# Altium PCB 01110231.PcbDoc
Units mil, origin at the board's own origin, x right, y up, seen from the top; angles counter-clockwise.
Board outline 3350 x 4325 mil, 2 copper layers (Top Layer, Bottom Layer); 143 components, 61 nets, 314 pads, 19 vias.
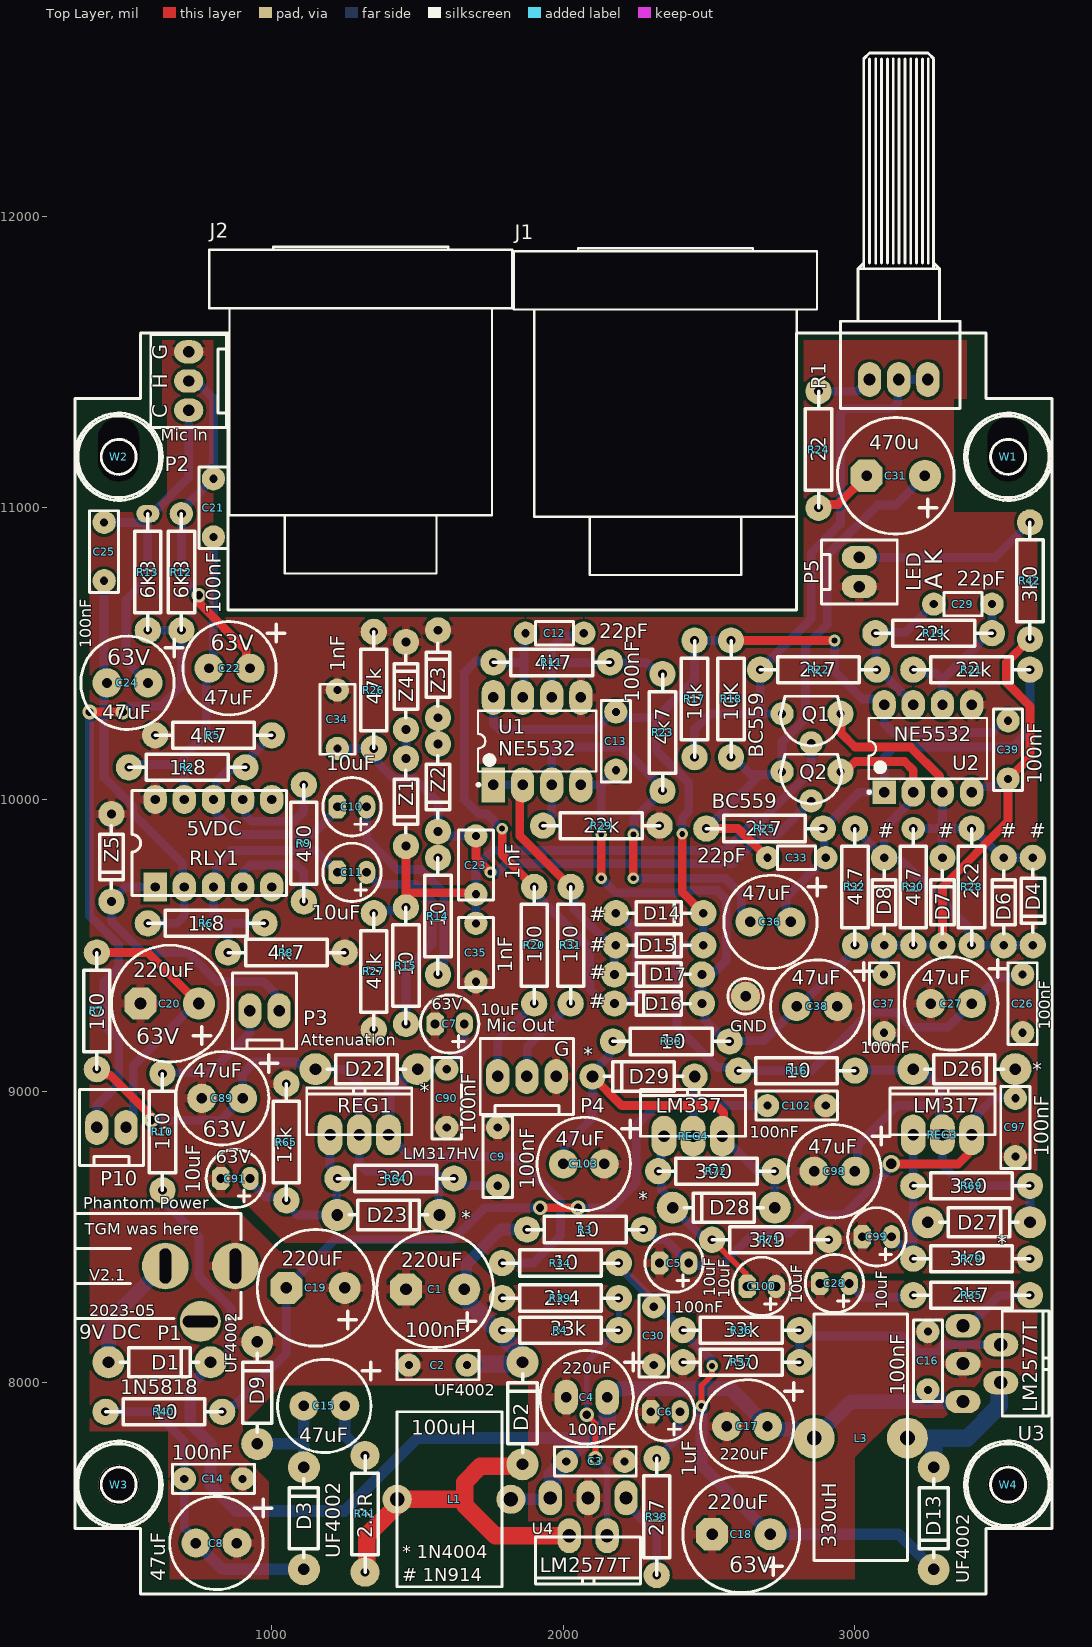
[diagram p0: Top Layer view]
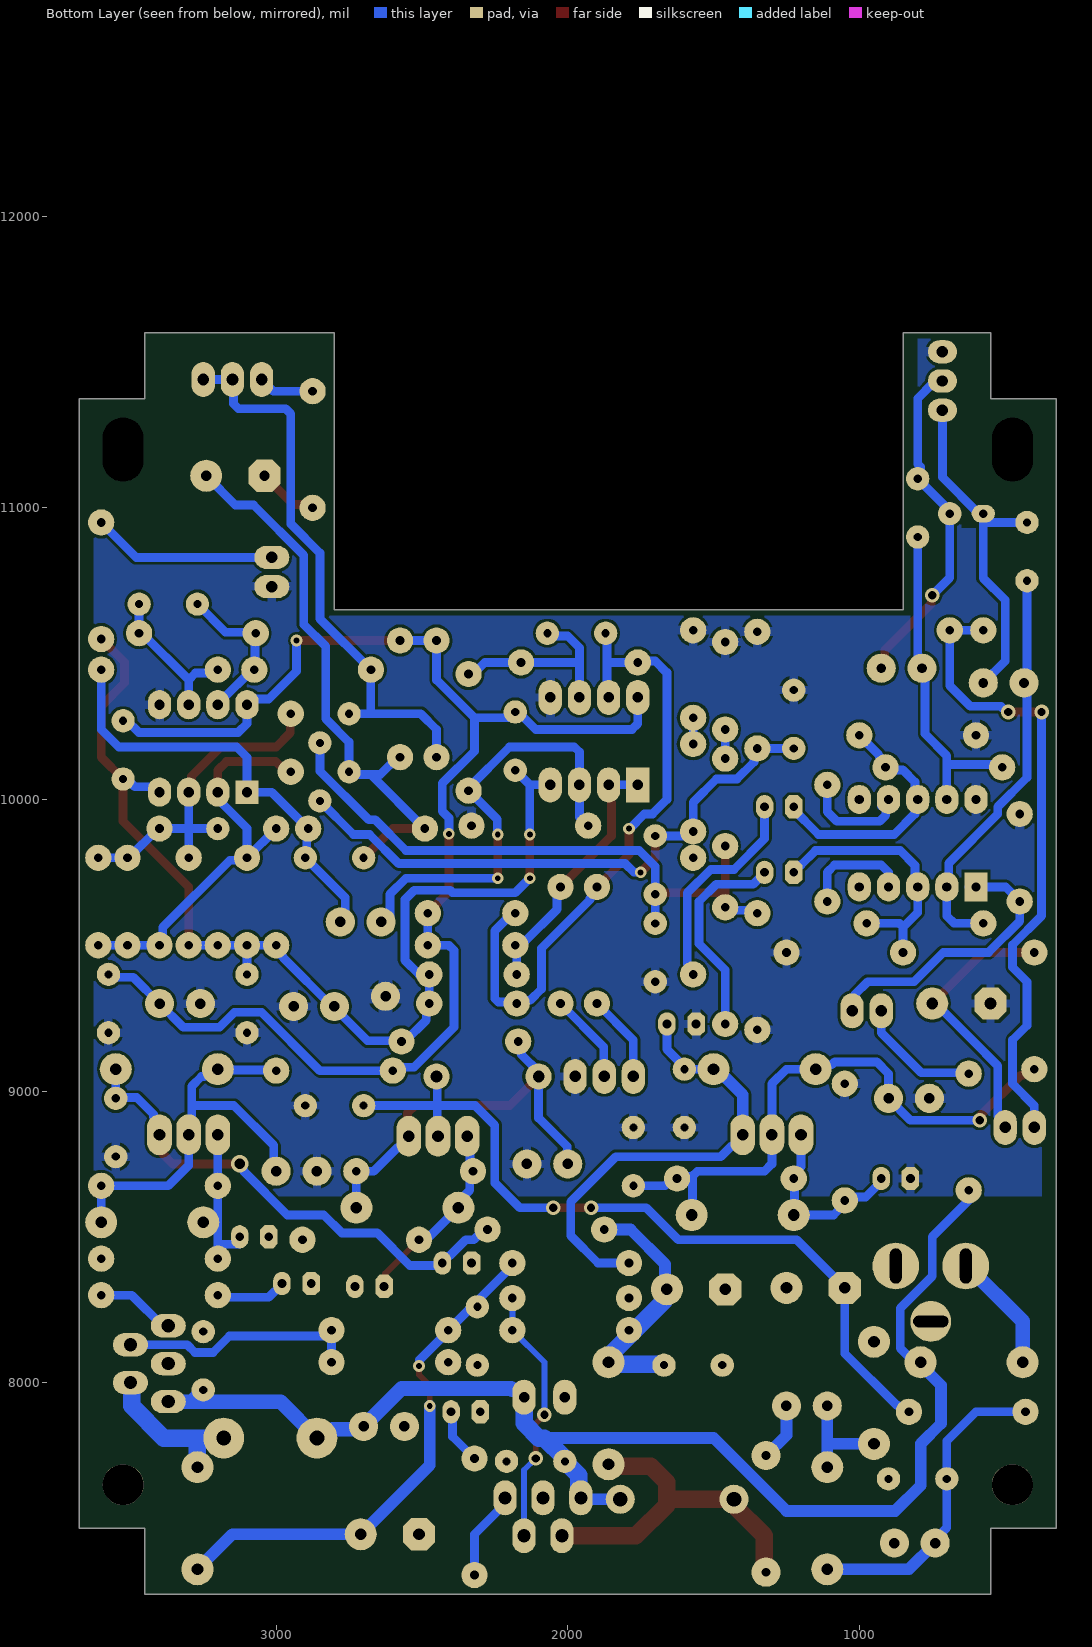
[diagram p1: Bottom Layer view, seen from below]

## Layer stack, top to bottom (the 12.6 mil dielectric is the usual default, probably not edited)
Top Solder: solder mask 0.4, Solder Resist, Dk 3.5
Top Layer: signal copper 1.4
Dielectric1: dielectric 12.6, FR-4, Dk 4.8
Bottom Layer: signal copper 1.4
Bottom Solder: solder mask 0.4, Solder Resist, Dk 3.5

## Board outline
325,7500 550,7500 550,7275 3450,7275 3450,7500 3675,7500 3675,11375 3450,11375 3450,11600 2800,11600 2800,10650 850,10650 850,11600 550,11600 550,11375 325,11375

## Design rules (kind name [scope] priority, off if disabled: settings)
Clearance Clearance_1 [All] p1: gap=10 ignorepadtopadclearanceinfootprint=TRUE
Clearance Clearance_poly [(IsRegion)] p2: gap=10 ignorepadtopadclearanceinfootprint=FALSE
DiffPairsRouting [All] p1: maxlimit=10 minlimit=10 mostfreqgap=10 toplayer_minwidth=15 toplayer_maxwidth=15 toplayer_prefwidth=15 bottomlayer_minwidth=15 bottomlayer_maxwidth=15 bottomlayer_prefwidth=15 substack1={E4759729-C15E-44EF-B839-1660CB1699A4} toplayer_{e4759729-c15e-44ef-b839-1660cb1699a4}_minwidth=15 toplayer_{e4759729-c15e-44ef-b839-1660cb1699a4}_maxwidth=15 toplayer_{e4759729-c15e-44ef-b839-1660cb1699a4}_prefwidth=15 bottomlayer_{e4759729-c15e-44ef-b839-1660cb1699a4}_minwidth=15 bottomlayer_{e4759729-c15e-44ef-b839-1660cb1699a4}_maxwidth=15 bottomlayer_{e4759729-c15e-44ef-b839-1660cb1699a4}_prefwidth=15 substack2={AF7D8FCE-D8A9-40D7-8453-C7F108753530} toplayer_{af7d8fce-d8a9-40d7-8453-c7f108753530}_minwidth=15 toplayer_{af7d8fce-d8a9-40d7-8453-c7f108753530}_maxwidth=15 toplayer_{af7d8fce-d8a9-40d7-8453-c7f108753530}_prefwidth=15 bottomlayer_{af7d8fce-d8a9-40d7-8453-c7f108753530}_minwidth=15 bottomlayer_{af7d8fce-d8a9-40d7-8453-c7f108753530}_maxwidth=15 bottomlayer_{af7d8fce-d8a9-40d7-8453-c7f108753530}_prefwidth=15 maxuncoupledlength=500
Height [All] p1: minheight=0 maxheight=1130 prefheight=500
HoleSize [All] p1: absolutevalues=TRUE maxlimit=400 minlimit=1 maxpercent=80.000 minpercent=20.000
PlaneConnect [All] p1: planeconnectstyle=Relief reliefexpansion=20 reliefentries=4 reliefconductorwidth=30 reliefairgap=10
PolygonConnect [All] p1: connectstyle=Relief reliefconductorwidth=30 reliefentries=4 polygonreliefangle="90 Angle" airgapwidth=10
RoutingVias [All] p1: holewidth=16 width=32 viastyle="Through Hole" minholewidth=8 minwidth=16 maxholewidth=200 maxwidth=200
SilkToSolderMaskClearance SilkscreenOverComponentPads [IsPad] p1: minsilkscreentomaskgap=10 clearancetoexposedcopper=TRUE
SolderMaskExpansion [All] p1: expansion=4 istentingtop=FALSE
Width [All] p1: maxlimit=250 minlimit=10 preferedwidth=40 substack1={E4759729-C15E-44EF-B839-1660CB1699A4} substack2={AF7D8FCE-D8A9-40D7-8453-C7F108753530}
25 further rules are at their usual default settings.

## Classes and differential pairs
component class "RESPIN Mic Interface": C10 C11 C12 C13 C20 C21 C22 C23 C24 C25 C26 C27 C29 C31 C33 C34 C35 C36 C37 C38 C39 D4 D6 D7 D8 D14 D15 D16 D17 J1 J2 P2 P3 P4 P5 P10 Q1 Q2 R1 R2 R5 R6 R7 R8 R9 R10 R11 R12 R13 R14 R15 R16 R17 R18 R19 R20 R21 R22 R23 R24 R25 R26 R27 R28 R29 R30 R31 R32 R33 R42 RLY1 U1 U2 Z1 Z2 Z3 Z4 Z5
component class "RESPIN Power Supply": C1 C2 C3 C4 C5 C6 C7 C8 C9 C14 C15 C16 C17 C18 C19 C28 C30 C89 C90 C91 C97 C98 C99 C100 C102 C103 D1 D2 D3 D9 D13 D22 D23 D26 D27 D28 D29 F2 L1 L3 L6 P1 R3 R4 R34 R35 R36 R37 R38 R39 R40 R41 R64 R65 R69 R70 R71 R72 REG1 REG3 REG4 U3 U4 W1 W2 W3 W4

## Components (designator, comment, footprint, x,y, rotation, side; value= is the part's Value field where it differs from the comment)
C1 "220uF" RB.2/.4#1 1660,8320 r0 top
C2 "100nF" AXIAL0.2-2.5mm-CAP 1670,8060 r180 top
C3 "100nF" AXIAL0.2-2.5mm-CAP 2010,7730 r0 top
C4 "220uF" RB3.5/8mm#1 2150,7950 r180 top
C5 "10uF" RB.1/.2-PTH 2430,8410 r0 top
C6 "1uF" RB.1/.2-PTH 2400,7900 r0 top
C7 "10uF" RB.1/.2-PTH 1660,9230 r0 top
C8 "47uF" RB3.5/8mm#2 880,7450 r180 top
C9 "100nF" AXIAL0.2-2.5mm-CAP 1775,8675 r90 top
C10 "10uF" RB.1/.2-PTH 1325,9975 r0 top
C11 "10uF" RB.1/.2-PTH 1325,9750 r0 top
C12 "22pF" AXIAL0.2 1870,10570 r0 top
C13 "100nF" AXIAL0.2-2.5mm-CAP 2180,10300 r270 top
C14 "100nF" AXIAL0.2-2.5mm-CAP 700,7670 r0 top
C15 "47uF" RB3.5/8mm#2 1250,7920 r180 top
C16 "100nF" AXIAL0.2-2.5mm-CAP 3250,7975 r90 top
C17 "220uF" RB3.5/8mm#2 2700,7850 r180 top
C18 "220uF" RB.2/.4#1 2710,7480 r0 top
C19 "220uF" RB.2/.4#1 1250,8325 r0 top
C20 "220uF" RB.2/.4#1 750,9300 r0 top
C21 "100nF" AXIAL0.2-2.5mm-CAP 800,11100 r270 top
C22 "47uF" RB3.5/8MM 925,10450 r180 top
C23 "1nF" AXIAL0.2-CAP 1700,9675 r90 top
C24 "47uF" RB3.5/8MM 575,10400 r180 top
C25 "100nF" AXIAL0.2-2.5mm-CAP 425,10950 r270 top
C26 "100nF" AXIAL0.2-2.5mm-CAP 3575,9400 r270 top
C27 "47uF" RB3.5/8mm#2 3400,9300 r180 top
C28 "10uF" RB.1/.2-PTH 2980,8340 r0 top
C29 "22pF" AXIAL0.2 3270,10670 r0 top
C30 "100nF" AXIAL0.2-2.5mm-CAP 2310,8260 r270 top
C31 "470u" RB.2/.4#2 3240,11110 r0 top
C33 "22pF" AXIAL0.2 2700,9800 r0 top
C34 "1nF" AXIAL0.2-CAP 1225,10375 r270 top
C35 "1nF" AXIAL0.2-CAP 1700,9375 r90 top
C36 "47uF" RB3.5/8mm#2 2780,9580 r180 top
C37 "100nF" AXIAL0.2-2.5mm-CAP 3100,9200 r90 top
C38 "47uF" RB3.5/8mm#2 2940,9290 r180 top
C39 "100nF" AXIAL0.2-2.5mm-CAP 3524.99,10270.01 r270 top
C89 "47uF" RB3.5/8mm#2 900,8975 r180 top
C90 "100nF" AXIAL0.2-2.5mm-CAP 1600,9075 r270 top
C91 "10uF" RB.1/.2-PTH 925,8700 r0 top
C97 "100nF" AXIAL0.2-2.5mm-CAP 3550,8975 r270 top
C98 "47uF" RB3.5/8mm#2 3000,8725 r180 top
C99 "10uF" RB.1/.2-PTH 3125,8500 r0 top
C100 "10uF" RB.1/.2-PTH 2730,8330 r0 top
C102 "100nF" AXIAL0.2-2.5mm-CAP 2900,8950 r180 top
C103 "47uF" RB3.5/8mm#2 2140,8750 r180 top
D1 "1N5818" DIODE0.35-TH#1 440,8070 r0 top
D2 "UF4002" DIODE0.35-TH#1 1860,7720 r90 top
D3 "UF4002" DIODE0.35-TH#1 1110,7360 r90 top
D4 "1N914" "DIODE0.3-TH - AK" 3610,9800 r270 top
D6 "1N914" "DIODE0.3-TH - AK" 3510,9500 r90 top
D7 "1N914" "DIODE0.3-TH - AK" 3300,9500 r90 top
D8 "1N914" "DIODE0.3-TH - AK" 3100,9500 r90 top
D9 "UF4002" DIODE0.35-TH#1 950,7790 r90 top
D13 "UF4002" DIODE0.35-TH#1 3270,7710 r270 top
D14 "1N914" "DIODE0.3-TH - AK" 2180,9610 r0 top
D15 "1N914" "DIODE0.3-TH - AK" 2180,9500 r0 top
D16 "1N914" "DIODE0.3-TH - AK" 2475,9300 r180 top
D17 "1N914" "DIODE0.3-TH - AK" 2475,9400 r180 top
D22 "1N4004" DIODE0.35-TH#1 1150,9075 r0 top
D23 "1N4004" DIODE0.35-TH#1 1225,8575 r0 top
D26 "1N4004" DIODE0.35-TH#1 3200,9075 r0 top
D27 "1N4004" DIODE0.35-TH#1 3250,8550 r0 top
D28 "1N4004" DIODE0.35-TH#1 2725,8600 r180 top
D29 "1N4004" DIODE0.35-TH#2 2450,9050 r180 top
J1 "XLR Panel Socket" "XLR_3 - Altronics P0850" 2350,10600 r0 top
J2 "XLR Panel Plug" "XLR_3 - Altronics P0850" 1305,10605 r0 top
L1 "100uH" INDUCTOR15MMx9MM-VERT 1790,7600 r180 top
L3 "330uH" INDUCTOR21mmx8mm-VERT 2860,7810 r0 top
P1 "Power" "2.1MM SOCKET" 875,8400 r180 top
P2 "Mic In" "HEADER 3 SIL"#1 715,11535 r270 top
P3 "Attenuation" "HEADER 2 SIL" 1025,9275 r180 top
P4 "Mic Out" "HEADER 3 SIL"#2 1975,9050 r180 top
P5 "LED" "Header 2 SIL" 3015,10730 r90 top
P10 "Phantom Power" "HEADER 2 SIL" 500,8875 r180 top
Q1 "BC559" TO-92BIG 2850,10193.87 r270 top
Q2 "BC559" TO-92BIG 2850,9995 r270 top
R1 "10K Reverse Log" "POT_Small_Single - TT Single Horizontal" 3150,11440 r180 top
R2 "1k8" AXIAL0.4#1 910,10110 r180 top
R3 "10" AXIAL0.4#1 1875,8525 r0 top
R4 "33k" AXIAL0.4#1 2190,8180 r180 top
R5 "4k7" AXIAL0.4#1 1000,10220 r180 top
R6 "1k8" AXIAL0.4#1 975,9575 r180 top
R7 "100" AXIAL0.4#1 400,9075 r90 top
R8 "4k7" AXIAL0.4#1 850,9475 r0 top
R9 "430" AXIAL0.4#1 1110,10050 r270 top
R10 "150" AXIAL0.4#1 625,9059.69 r270 top
R11 "4k7" AXIAL0.4#1 1760,10470 r0 top
R12 "6K8" AXIAL0.4#2 690,10980 r270 top
R13 "6K8" AXIAL0.4#3 575,10980 r270 top
R14 "10" AXIAL0.4#1 1570,9400 r90 top
R15 "10" AXIAL0.4#1 1460,9230 r90 top
R16 "10" AXIAL0.4#1 3000,9070 r180 top
R17 "10k" AXIAL0.4#1 2450,10145 r90 top
R18 "10K" AXIAL0.4#1 2575,10145 r90 top
R19 "22k" AXIAL0.4#1 3070,10570 r0 top
R20 "100" AXIAL0.4#1 1900,9700 r270 top
R21 "22k" AXIAL0.4#1 3200,10445 r0 top
R22 "2k7" AXIAL0.4#1 2675,10445 r0 top
R23 "4k7" AXIAL0.4#1 2340,10430 r270 top
R24 "22" AXIAL0.4#1 2875,11400 r270 top
R25 "2k7" AXIAL0.4#1 2490,9900 r0 top
R26 "47k" AXIAL0.4#1 1350,10175 r90 top
R27 "47k" AXIAL0.4#1 1350,9610 r270 top
R28 "2k2" AXIAL0.4#1 3400,9900 r270 top
R29 "22k" AXIAL0.4#1 2330,9910 r180 top
R30 "4K7" AXIAL0.4#4 3200,9500 r90 top
R31 "100" AXIAL0.4#1 2025,9700 r270 top
R32 "4K7" AXIAL0.4#1 3000,9500 r90 top
R33 "10" AXIAL0.4#1 2170,9170 r0 top
R34 "10" AXIAL0.4#1 2190,8410 r180 top
R35 "2k7" AXIAL0.4#1 3200,8300 r0 top
R36 "33k" AXIAL0.4#1 2810,8180 r180 top
R37 "750" AXIAL0.4#1 2410,8070 r0 top
R38 "2k7" AXIAL0.4#1 2320,7740 r270 top
R39 "2k4" AXIAL0.4#1 1790,8290 r0 top
R40 "10" AXIAL0.4#1 430,7900 r0 top
R41 "2.2R" AXIAL0.4#5 1320,7350 r90 top
R42 "3k0" AXIAL0.4#1 3600,10950 r270 top
R64 "330" AXIAL0.4#1 1225,8700 r0 top
R65 "12k" AXIAL0.4#1 1050,9025 r270 top
R69 "390" AXIAL0.4#1 3200,8675 r0 top
R70 "3k9" AXIAL0.4#1 3600,8425 r180 top
R71 "3k9" AXIAL0.4#1 2510,8490 r0 top
R72 "390" AXIAL0.4#1 2725,8725 r180 top
REG1 "LM317HV" TO-220-REG 1300,8850 r0 top
REG3 "LM317" TO-220-REG 3300,8850 r0 top
REG4 "LM337" TO-220-REG 2444.99,8845 r0 top
RLY1 "5VDC" DIP10 600,9700 r90 top (schematic designator RL1)
U1 "NE5532" DIP-8#1 1910,10200 r90 top
U2 "NE5532" DIP-8#2 3250,10175 r90 top
U3 "LM2577T" "TO-220 - 5PIN" 3520,8065 r270 top
U4 "LM2577T" "TO-220 - 5pin" 2085,7455 r180 top
W1 "Washer" "M3 Crinkle" 3525,11175 r0 top
W2 "Washer" "M3 Crinkle" 475,11175 r0 top
W3 "Washer" "M3 Crinkle" 475,7650 r0 top
W4 "Washer" "M3 Crinkle" 3525,7650 r0 top
Z1 "6V8" "DIODE0.3-TH - AK" 1460,10140 r270 top
Z2 "6V8" "DIODE0.3-TH - AK" 1570,10190 r270 top
Z3 "6V8" "DIODE0.3-TH - AK" 1570,10280 r90 top
Z4 "6V8" "DIODE0.3-TH - AK" 1460,10240 r90 top
Z5 "6V8" "DIODE0.3-TH - AK" 450,9950 r270 top

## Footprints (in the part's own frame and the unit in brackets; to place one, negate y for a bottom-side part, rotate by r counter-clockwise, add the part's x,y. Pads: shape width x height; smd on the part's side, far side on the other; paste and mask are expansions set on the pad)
"2.1MM SOCKET" [mil] "Altronics P0620 Socket"
  round 160 hole 40 slot 120 at 90 deg: 1(0,0) 2(240,0)
  round 140 hole 40 slot 120 at 0 deg: 3(120,190)
  silkscreen extent -20,-180 550,180, body extent -25,-185 555,185, height 400
AXIAL0.2 [mil]
  round 80 hole 28: 1(0,0) 2(200,0)
  silkscreen extent 35,-40 165,40, body extent 30,-45 170,45, height 200
AXIAL0.2-2.5mm-CAP [mil]
  round 80 hole 28: 1(0,0) 2(200,0)
  silkscreen extent -40,-50 240,50, body extent -40,-50 240,50, height 200
AXIAL0.2-CAP [mil]
  round 80 hole 28: 1(0,0) 2(200,0)
  silkscreen extent -20,-60 220,60, body extent -25,-65 225,65, height 200
AXIAL0.4#1 [mil] "resistor"
  round 90 hole 30: 1(0,0) 2(400,0)
  silkscreen extent 0,-45 400,45, body extent -5,-50 405,50, height 100
AXIAL0.4#2 [mil] "resistor"
  round 80 hole 30: 1(0,0)
  round 90 hole 30: 2(400,0)
  silkscreen extent 0,-45 400,45, body extent -5,-50 405,50, height 100
AXIAL0.4#3 [mil] "resistor"
  oval 60x80 hole 30: 1(0,0)
  round 90 hole 30: 2(400,0)
  silkscreen extent 0,-45 400,45, body extent -5,-50 405,50, height 100
AXIAL0.4#4 [mil] "resistor"
  round 90 hole 30: 1(0,0)
  round 80 hole 30: 2(400,0)
  silkscreen extent 0,-45 400,45, body extent -5,-50 405,50, height 100
AXIAL0.4#5 [mil] "resistor"
  round 100 hole 30: 1(0,0) 2(400,0)
  silkscreen extent 0,-45 400,45, body extent -5,-50 405,50, height 100
"DIODE0.3-TH - AK" [mil] "DO-35 Footprint"
  round 90 hole 30: A(0,0) K(300,0)
  silkscreen extent 40,-40 255,40, body extent -15,-40 315,40, height 95
DIODE0.35-TH#1 [mil]
  round 110 hole 40: 1(0,0) 2(350,0)
  silkscreen extent 40,-50 310,50, body extent -15,-55 365,55, height 110
DIODE0.35-TH#2 [mil]
  round 90 hole 40: 1(0,0) 2(350,0)
  silkscreen extent 40,-50 310,50, body extent -15,-55 365,55, height 110
DIP10 [mil] "DPDT signal relay"
  rect 100x80 hole 32: 1(0,0)
  oval 100x80 hole 32: 2(0,-100) 3(0,-200) 4(0,-300) 5(0,-400) 6(300,-400) 7(300,-300) 8(300,-200) 9(300,-100) 10(300,0)
  silkscreen extent -30,-450 330,80, body extent -30,-450 330,80, height 300
DIP-8#1 [mil] "DIP; 8 Leads; Row Spacing 7.62 mm; Pitch 2.54 mm"
  rect 120x80 hole 36: 1(-150,150)
  oval 120x80 hole 36: 2(-150,50) 3(-150,-50) 4(-150,-150) 5(150,-150) 6(150,-50) 7(150,50) 8(150,150)
  silkscreen extent -155,-203 104,206, body extent -142,-203 142,203, height 200
DIP-8#2 [mil] "DIP; 8 Leads; Row Spacing 7.62 mm; Pitch 2.54 mm"
  rect 80x80 hole 35.43: 1(-150,150)
  oval 100x80 hole 35.43: 2(-150,50) 3(-150,-50) 4(-150,-150) 5(150,-150) 6(150,-50) 7(150,50) 8(150,150)
  silkscreen extent -155,-203 104,206, body extent -142,-203 142,203, height 200
"HEADER 2 SIL" [mil] "Altronics P5494"
  oval 80x120 hole 39.37: 1(0,0) 2(100,0)
  silkscreen extent -60,-130 160,130, body extent -65,-135 160,135, height 460
"Header 2 SIL" [mil] "Altronics P5494"
  oval 80x120 hole 39.37: 1(0,0) 2(100,0)
  silkscreen extent -60,-130 160,130, body extent -65,-135 160,135, height 460
"HEADER 3 SIL"#1 [mil] "Altronics P5494"
  oval 80x100 hole 39.37: 1(0,0) 2(100,0) 3(200,0)
  silkscreen extent -60,-130 260,130, body extent -65,-135 260,135, height 460
"HEADER 3 SIL"#2 [mil] "Altronics P5494"
  oval 80x120 hole 39.37: 1(0,0) 2(100,0) 3(200,0)
  silkscreen extent -60,-130 260,130, body extent -65,-135 260,135, height 460
INDUCTOR15MMx9MM-VERT [mil]
  round 100 hole 50: 1(-30,0) 2(360,0)
  silkscreen extent 0,-300 360,300, body extent 0,-300 360,300, height 600
INDUCTOR21mmx8mm-VERT [mil]
  round 140 hole 50: 1(0,0) 2(320,0)
  silkscreen extent 0,-420 320,425, body extent 0,-420 320,420, height 840
"M3 Crinkle" [mil] "M3 Crinkle Washer"
  silkscreen extent -140,-140 140,140, body extent -140,-140 140,140, height 20
"POT_Small_Single - TT Single Horizontal" [mil] "Bourns PTV111-1 Single Turn Small"
  oval 80x120 hole 40: 1(-100,0) 2(0,0) 3(100,0)
  silkscreen extent -210,-1120 200,100, body extent -210,-1125 200,100, height 500
RB3.5/8mm#1 [mil]
  oval 80x120 hole 36: 1(0,0) 2(140,0)
  silkscreen extent -120,-160 230,160, body extent -90,-160 230,160, height 450
RB3.5/8mm#2 [mil]
  round 100 hole 36: 1(0,0) 2(140,0)
  silkscreen extent -120,-160 230,160, body extent -90,-160 230,160, height 450
RB3.5/8MM [mil]
  round 100 hole 34: 1(0,0) 2(140,0)
  silkscreen extent -120,-160 230,160, body extent -90,-160 230,160, height 450
RB.1/.2-PTH [mil]
  oval 60x80 hole 30: 1(0,0)
  oct 60x80 hole 30: 2(-100,0)
  silkscreen extent -150,-100 50,100, body extent -150,-100 50,100, height 300
RB.2/.4#1 [mil]
  round 110 hole 40: 1(0,0)
  oct 110x110 hole 40: 2(-200,0)
  silkscreen extent -300,-200 100,200, body extent -300,-200 100,200, height 1000
RB.2/.4#2 [mil]
  round 110 hole 36: 1(0,0)
  oct 110x110 hole 36: 2(-200,0)
  silkscreen extent -300,-200 100,200, body extent -300,-200 100,200, height 1000
TO-92BIG [mil]
  round 80 hole 28: B(0,0) E(-100,-100)
  round 90 hole 28: C(-100,100)
  silkscreen extent -160,-105 10,105, body extent -160,-110 10,110, height 500
"TO-220 - 5PIN" [mil]
  oval 80x120 hole 45: 1(-130,-150) 2(-65,-20) 3(0,-150) 4(65,-20) 5(130,-150)
  silkscreen extent -180,-15 180,145, body extent -180,-160 180,145, height 950
"TO-220 - 5pin" [mil]
  oval 80x120 hole 45: 1(-130,-150) 2(-65,-20) 3(0,-150) 4(65,-20) 5(130,-150)
  silkscreen extent -180,-15 180,145, body extent -180,-160 180,145, height 950
TO-220-REG [mil]
  oval 85x140 hole 40: 1(-100,0) 2(-0.12,0.2) 3(100,0)
  silkscreen extent -180,0 180,160, body extent -180,0 180,160, height 800
"XLR_3 - Altronics P0850" [mil] "3 Pin XLR Female Connector"
  silkscreen extent -520,170 520,1290, body extent -525,170 526,1280, height 1220

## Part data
C1 C18 C19 C20: library part "CAPACITOR POL", "Altronics p/n R5148"
C2 C3 C9 C13 C14 C16 C21 C25 C26 C30 C37 C39 C90 C97 C102: library part CAP, "Altronics p/n R3025B"
C4 C17: library part "CAPACITOR POL", "Altronics p/n R5144"
C5 C10 C11 C28 C99 C100: library part CAPACITOR, "Altronics p/n R6067"
C6: library part CAPACITOR, "Altronics p/n R4718"
C7 C91: library part CAPACITOR, "Altronics p/n R4768"
C8 C15 C27 C36 C38 C89 C98 C103: library part "CAPACITOR POL", "Altronics p/n R5108"
C12 C29 C33: library part CAP, "Altronics p/n R2814"
C22 C24: library part CAPACITOR, "Altronics p/n R5108"
C23 C34 C35: library part CAP, "Altronics p/n R3001B"
C31: library part CAPACITOR, "Altronics p/n R5164"
D1: library part DIODE_Numbered, "Altronics p/n Z0040"
D2 D3 D9 D13: library part DIODE_Numbered, "Altronics p/n Z0030"
D4 D6 D7 D8 D14 D15 D16 D17: library part DIODE, "Altronics p/n Z0101"
D22 D26: library part DIODE_Numbered, "Altronics p/n Z0109"
D23 D27 D28 D29: library part DIODE, "Altronics p/n Z0109"
J1: library part "XLR_3 Altronics P0850", "Altronics p/n P0850"
J2: library part "XLR_3 Altronics P0850", "Altronics p/n P0852"
L1: library part INDUCTOR, "Altronics p/n L6522"
L3: library part INDUCTOR, "Altronics p/n L6527 or Mouser p/n 542-2118-V-RC"
P1: library part "Header 2", "Altronics p/n P0620"
P2 P4: library part "Header 3", "Altronics p/n  P5493 + P5473"
P3 P5 P10: library part CON2, "Altronics p/n  P5492 + P5472"
Q1 Q2: library part PNP, "Altronics p/n Z1057"
R1: library part POT-SINGLE, "Mouser p/n  858-P091NFC25CR10K or 652-PTD9012015FC103"
R2 R6: library part RES2, "Altronics p/n R7564"
R3 R34 R40: library part RES2, "Altronics p/n Z7510"
R4 R36: library part RES2, "Altronics p/n R7594"
R5 R8 R11 R23 R30 R32: library part RES2, "Altronics p/n R7574"
R7: library part RES2, "Altronics p/n Z7534"
R9: library part RES2, "Altronics p/n R7551"
R10: library part RES2, "Altronics p/n R7538"
R12 R13: library part RES2, "Altronics p/n R7778"
R14 R15 R16 R33: library part RES2, "Altronics p/n R7510"
R17 R18: library part RES2, "Altronics p/n R7582"
R19 R21 R29: library part RES2, "Altronics p/n R7590"
R20 R31: library part RES2, "Altronics p/n R7534"
R22 R25 R35 R38: library part RES2, "Altronics p/n R7568"
R24: library part RES2, "Altronics p/n R7518"
R26 R27: library part RES2, "Altronics p/n R7598"
R28: library part RES2, "Altronics p/n R7566"
R37: library part RES2, "Altronics p/n R7555"
R39: library part RES2, "Altronics p/n R7567"
R41: library part RES2, "Altronics p/n Z7014"
R42: library part RES2, "Altronics p/n R7569"
R64: library part RES2, "Altronics p/n R7546"
R65: library part RES2, "Altronics p/n R7584"
R69 R72: library part RES2, "Altronics p/n R7548"
R70 R71: library part RES2, "Altronics p/n R7572"
REG1: library part LM317, "Altronics p/n Z0545"
REG3: "Altronics p/n Z0545"
REG4: "Altronics p/n Z0562"
RLY1: library part RELAY-DPDT_OMRON, "Altronics p/n S4128B"
U1 U2: library part LF353, "Altronics p/n Z2785"
U3 U4: library part LM2577T-ADJ/NOPB, "Jaycar p/n ZV1640", Manufacturer="National Semiconductor", PackageTopMarking=NSUZXYTTE#*LM2577T*-ADJ*P+, PowerWise=N, Supplier Part Number 1=LM2577T-ADJ-ND
W1 W2 W3 W4: "Altronics p/n H3185"
Z1 Z2 Z3 Z4 Z5: library part ZENER2, "Altronics p/n Z0320"

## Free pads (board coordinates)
  round 140 hole 140: 3(475,7650) 3(3525,7650)
  round 120 hole 140 slot 220 at 90 deg: 3(475,11200) 3(3525,11200)
  round 100 hole 36: 4(2625,9325)

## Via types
v1: diameter 40, hole 20, Top Layer to Bottom Layer, tented both sides, 10 vias
v2: diameter 50, hole 28, Top Layer to Bottom Layer, tented both sides, 8 vias
v3: diameter 60, hole 36, Top Layer to Bottom Layer, 1 vias

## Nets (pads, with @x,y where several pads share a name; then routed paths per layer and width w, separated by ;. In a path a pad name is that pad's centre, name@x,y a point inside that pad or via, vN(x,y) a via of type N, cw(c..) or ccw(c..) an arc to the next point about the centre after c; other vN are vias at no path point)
48V: C9.1 C89.1 D22.1 D23.2 R7.1 R64.2 REG1.2 | length 2071.1
  Top Layer w30: R7.1 416.24,9075 436.67,9054.57 446.85,9054.57 583.54,8917.88 583.54,8903.83 v2(587.37,8900)
  Bottom Layer w30: R7.1 R7.1@412.37,9075 ; v2(587.37,8900) 825,8900 C89.1 900,9059.69 940.31,9100 1084.61,9100 1094.3,9090.31 1134.69,9090.31 D22.1 1250,9075 1299.88,9025.12 REG1.2 1299.88,8750.12 1325,8725 1554.93,8725 1572.5,8707.43 ; D23.2 1572.5,8577.5 1572.5,8707.43 ; C9.1 1666.24,8675 1641.24,8700 R64.2 1617.57,8707.43 1572.5,8707.43
"+DC Prot": C3.1 C4.1 C16.1 C17.1 D1.2 L1.1 L3.1 R10.2 U3.5 U4.5 | length 4616
  Bottom Layer w30: R10.2 621.21,8655.9 621.21,8628.79 750,8500 750,8365 860,8255 860,8118.35 811.65,8070 D1.2@800,8070
  Bottom Layer w40: D1.2 790,8061.57 720,7991.57 720,7860 790,7790 790,7647.36 877.36,7560 1250,7560 1500,7810 2080,7810 ; L1.1 1950,7600 U4.5@1962.65,7612.65
  Bottom Layer w50: C4.1@2150,7961.88 2163.86,7975.74 2190.03,7975.74 2194.29,7980 2570,7980 C17.1 2709.57,7840.43 2805.21,7840.43 2835.65,7810 L3.1 2985,7935 3289.48,7935 ; C16.1 3250,7974.48 3289.48,7935 ; U3.5 3289.48,7935
  Bottom Layer w60: U4.5@1962.65,7612.65 1958.83,7616.48 1958.83,7642.97 1962.65,7646.8 1962.65,7682.65 C3.1 2010,7740 2080,7810 2100,7810 2150,7860 C4.1
+V_filt_2: C13.1 C26.1 C27.1 C39.1 D14.K D15.K R16.2 R17.2 R18.2 U1.8 U2.8 | length 4970.7
  Top Layer w30: v1(2407.57,9881.91) 2407.57,9682.43 D14.K ; R18.2 v1(2930,10545)
  Bottom Layer w30: U1.8 1760,10260 1780,10240 2110,10240 2170,10300 C13.1 ; C13.1@2180,10280 2320,10280 ; v1(2407.57,9881.91) 2407.57,9937.57 2430,9960 2430,10055 2320,10165 2320,10280 ; D14.K@2479.85,9605.15 2479.85,9500.15 D15.K 2407.57,9500 2390,9482.43 2390,9218.52 2527.04,9081.48 2588.52,9081.48 R16.2 2850,9070 3050,9270 3143.12,9270 3194.6,9218.52 3318.52,9218.52 C27.1 3490.43,9390.43 3565.43,9390.43 C26.1 ; R18.2 R17.2 2450,10410 2320,10280 ; v1(2930,10545) 2930,10440 3025.43,10344.57 3080.43,10344.57 U2.8 3100,10260 3130,10230 3471.45,10230 3511.46,10270.01 C39.1
+VREG: C98.1 D26.1 D27.2 R16.1 R69.2 REG3.2 | length 1475.5
  Bottom Layer w30: C98.1 3008.69,8733.69 3008.69,8813.69 3145.35,8950.35 3289.48,8950.35 ; R16.1 3002.5,9072.5 3197.5,9072.5 D26.1 3221.65,9075 3246.73,9049.91 3256.34,9049.91 3289.48,9016.77 3289.48,8950.35 ; D27.2 R69.2 3370,8675 3300,8745 3300,8850 3289.48,8860.52 3289.48,8950.35
-V_filt_2: C13.2 C37.2 C38.2 C39.2 D7.A D8.A D16.A D17.A R30.1 R32.1 R33.2 R42.2 U1.4 U2.4 | length 3878.9
  Top Layer w30: v1(2130,9730) v1(2130,9880) ; D7.A 3300,9700 3524.99,9924.99 C39.2 3600,10145.02 3600,10320 3520,10400 3520,10470 R42.2
  Bottom Layer w30: U1.4 2130,10050 ; v1(2130,9730) 2180,9680 2395.01,9680 2403.53,9688.52 2526.47,9688.52 2558.52,9656.47 2558.52,9448.52 2510,9400 D17.A D16.A 2485.4,9289.6 2485.4,9243.12 2558.52,9170 R33.2 2572.24,9172.24 2686.97,9172.24 2800,9285.26 C38.2 2808.52,9290 2975.62,9457.1 2975.62,9459.38 3000,9483.76 R32.1 D8.A ; v1(2130,9880) 2130,10050 ; C13.2 2130,10050 ; C37.2 D8.A ; D7.A R30.1 D8.A ; U2.4 3418.55,10043.55 3485,10043.55 3511.46,10070.01 C39.2
-VREG: C103.2 D28.1 D29.2 R33.1 R72.1 REG4.3 | length 1476.8
  Top Layer w30: D29.2 2200,8950 2525,8950 2550,8925 2550,8850.01 REG4.3
  Bottom Layer w30: C103.2 2002.12,8752.12 2002.12,8809.54 2100,8907.43 2100,8950.12 2100,9066.24 2158.52,9124.76 2158.52,9163.89 R33.1@2170,9175.38 ; REG4.3@2544.99,8880.01 REG4.3 2544.99,8832.38 2570.4,8806.98 2583.01,8806.98 2664.99,8725 R72.1 D28.1
C: C24.1 C25.1 P2.3 R13.1 | length 1218.1
  Bottom Layer w30: C25.1 R13.1@575,10950 ; C24.1 500,10475 500,10683.76 575,10758.76 R13.1@575,10950 ; P2.3@725,11335 715,11325 715,11105 590,10980 R13.1 R13.1@575,10950
GND: C1.2 C2.2 C3.2 C4.2 C5.2 C6.2 C7.2 C8.1 C9.2 C14.2 C16.2 C17.2 C18.2 C19.1 C20.2 C26.2 C27.2 C28.2 C30.2 C34.1 C35.1 C37.1 C38.1 C89.2 C90.2 C91.2 C97.2 C98.2 C99.2 C100.1 C102.1 C103.1 D9.2 P1.1 P2.1 P4.1 P5.1 pad.4 R5.2 R8.2 R26.2 R27.2 R29.1 R37.1 R39.1 R65.1 R70.1 R71.2 RLY1.10 U1.5 U2.5 U3.3 U4.3 Z3.K Z4.K Z5.A
H: C21.1 C22.1 P2.2 R12.1 | length 1166.3
  Top Layer w30: v2(750,10700) 753.83,10696.17 753.83,10671.17 912.82,10512.18 912.82,10462.18 C22.1
  Bottom Layer w30: P2.2 724.57,11425.43 749.57,11425.43 800,11375 800,11150 790.43,11140.43 C21.1@790.43,11115.43 ; v2(750,10700) 690,10760 690,10990 C21.1
MIC: C36.2 R23.2 R29.2 U1.3 | length 1570.6
  Top Layer w30: v1(2240,9730) v1(2240,9880) ; R23.2@2340,10013.76 R23.2
  Bottom Layer w30: R29.2 1960,9940 U1.3 1960,10162.43 1977.57,10180 2200,10180 2340,10040 R23.2 2241.91,9931.91 2241.91,9881.91 v1(2240,9880) ; v1(2240,9730) 2554.99,9730 2610,9674.99 C36.2@2610,9575
Mic_Out_C: P4.3 R20.2 | length 301.8
  Bottom Layer w30: P4.3 1775,9175 R20.2
Mic_Out_H: P4.2 R31.2 | length 325.7
  Bottom Layer w30: P4.2@1865.43,9040.43 P4.2 1876.24,9051.24 1876.24,9151.24 R31.2
NetC1_1: C1.1 C2.1 D2.2 R3.1 R4.2 | length 898.1
  Top Layer w60: D2.2@1846.47,8070 D2.2
  Bottom Layer w40: C1.1@1660,8330 1666.32,8336.32 1666.32,8406.32 1785,8525 R3.1
  Bottom Layer w60: C1.1@1660,8330 1669.57,8320.43 1669.57,8281.26 1860,8090.82 D2.2 ; C2.1 1673.83,8063.83 1853.83,8063.83 D2.2 ; D2.2@1860,8059.17 D2.2
NetC5_1: C5.1 C97.1 D26.2 R3.2 REG3.3 | length 1734.9
  Top Layer w30: v3(3125,8750) 3354.33,8750 3389.48,8785.15 3389.48,8839.48 REG3.3
  Bottom Layer w30: R3.2 2287.57,8525 2322.57,8490 2350,8490 2405,8435 2406.88,8435 2430,8411.88 C5.1 2438.25,8401.75 2541.75,8401.75 2653.52,8513.52 2775,8513.52 2836.48,8575 2961.47,8575 3110,8723.53 3110,8726.88 3125,8741.88 v3(3125,8750) ; REG3.3 3400,8892.38 3420.62,8913 3420.62,8920.62 3478.02,8978.02 3546.98,8978.02 C97.1 D26.2
NetC6_1: C6.1 R38.1 | length 209.4
  Bottom Layer w30: R38.1@2320,7756.24 R38.1 2395,7815 2395,7895 C6.1
NetC7_1: C7.1 C90.1 D22.2 R34.2 REG1.3 | length 1583.8
  Bottom Layer w30: REG1.3 1400,8837.38 1425.41,8811.98 1438.02,8811.98 1475,8775 1835,8775 1990,8620 1990,8503.5 1896.5,8410 R34.2 ; D22.2 C90.1 1600,9083.76 1660,9143.76 C7.1
  Bottom Layer w40: REG1.3 1400,8987.37 1475,9062.37 D22.2@1475,9075
NetC8_2: C8.2 C14.1 D3.1 R40.1 | length 1085.3
  Bottom Layer w30: R40.1 600,7900 700,7800 C14.1 700,7502.57 740,7462.57 C8.2
  Bottom Layer w40: C8.2 830,7360 D3.1
NetC10_1: C10.1 R14.1 | length 739.9
  Bottom Layer w30: C10.1 1325,9865 1430,9760 1510,9760 1590,9680 1590,9436.24 1570,9416.24 R14.1
NetC10_2: C10.2 R2.1 R5.1 RLY1.8 | length 860.3
  Bottom Layer w30: R2.1@901.36,10101.36 851.36,10101.36 809.57,10059.57 809.57,10009.57 RLY1.8 809.57,9990.43 809.57,9950.43 880,9880 1140,9880 C10.2@1230,9970 ; R2.1 910,10126.24 933.64,10149.88 933.64,10153.64 R5.1
NetC11_1: C11.1 R15.1 | length 732.6
  Bottom Layer w30: C11.1@1330.53,9744.47 C11.1 1325,9748.12 1363.55,9709.57 1490.43,9709.57 1550,9650 1550,9505 1460,9415 R15.1
NetC11_2: C11.2 R6.1 R8.1 RLY1.3 | length 924.1
  Bottom Layer w30: R8.1 850,9562.37 ; R6.1 862.63,9575 850,9562.37 ; C11.2 1225,9753.79 1203.79,9775 1200,9775 1150,9825 860,9825 809.57,9774.57 809.57,9709.57 RLY1.3 800,9612.37 850,9562.37
NetC12_1: C12.1 D14.A D16.K R11.1 R20.1 U1.7 | length 2233.7
  Top Layer w30: v1(1790,9900) 1790,9810 R20.1
  Bottom Layer w30: v1(1790,9900) 1787.29,9900 1736.86,9950.43 1709.57,9950.43 1660,10000 1660,10435 1700,10475 1755,10475 R11.1 1865,10470 ; U1.7 1865,10355 1865,10470 ; C12.1 1865,10565 1865,10470 ; R20.1 1900,9683.76 1923.64,9660.12 1923.64,9656.36 2090,9490 2090,9350 2128.52,9311.48 2163.52,9311.48 D16.K 2179.93,9304.93 2237.35,9304.93 2250,9317.57 2250,9550 D14.A@2190,9610
NetC12_2: C12.2 R11.2 R23.1 U1.6 | length 697.3
  Bottom Layer w30: U1.6 1960,10470 ; C12.2 2060.43,10560.43 2000.43,10560.43 1960,10520 1960,10470 ; R23.1 2323.76,10430 2283.76,10470 R11.2 1960,10470
NetC15_1: C15.1 R41.2 | length 199
  Bottom Layer w40: C15.1 1250,7820 R41.2
NetC15_2: C15.2 D3.2 D9.1 | length 370
  Bottom Layer w40: D9.1 1110,7790 ; D3.2 1110,7790 ; C15.2 1110,7790
NetC18_1: C18.1 C30.1 D13.2 R34.1 R36.2 | length 1745.3
  Top Layer w20: v1(2473.52,7920) 2473.52,7990.52 2509.77,8026.77 2509.77,8057.03 v1(2510,8057.26)
  Bottom Layer w30: R34.1 2190,8400 R36.2 2410,8176.71 2508.09,8078.62 2508.09,8059.17 v1(2510,8057.26)
  Bottom Layer w40: v1(2473.52,7920) 2473.52,7716.48 C18.1 ; C18.1@2750,7480 3150,7480 D13.2
NetC19_2: C19.2 C102.2 D29.1 R40.2 REG4.2 | length 2763.9
  Top Layer w30: v2(1920,8600) v2(2050,8600) ; REG4.2 REG4.2@2447.44,8847.76 ; D29.1@2447.44,9047.44 D29.1
  Bottom Layer w30: R40.2 846.24,7900 869.88,7923.64 873.64,7923.64 1050,8100 C19.2 1215,8490 1620.82,8490 1730.82,8600 v2(1920,8600) ; v2(2050,8600) 2165,8600 2250,8685 2250,8882.43 2317.57,8950 2445.04,8950 2447.44,8947.6 ; REG4.2 2447.44,8847.76 2447.44,8947.6 ; 2447.44,8950 C102.2 ; D29.1@2447.44,9047.44 2447.44,8947.6
NetC20_1: C20.1 P10.1 R7.2 | length 958.1
  Top Layer w30: R7.2 575,9475 C20.1
  Bottom Layer w30: P10.1 500,8888.53 525,8913.53 525,9087.12 612.88,9175 737.88,9300 C20.1
NetC21_2: C21.2 C22.2 R2.2 RLY1.9 | length 1139.7
  Bottom Layer w30: R2.2 520,10120 700,10120 ; RLY1.9 700,10120 ; C22.2@775,10450 800,10475 C21.2 ; C22.2 775,10440 775,10225 700,10150 700,10120
NetC23_1: C23.1 C35.2 Q1.B R15.2 R27.1 Z1.K | length 2152.4
  Top Layer w30: R15.2 1460,9680 ; Z1.K 1460,9680 ; C23.1@1700,9680 C23.1 1695,9680 1460,9680
  Bottom Layer w30: R27.1 1360,9620 1450,9620 R15.2 ; C35.2 C23.1 1700,9770 1755,9825 2555,9825 2660,9930 2682.5,9930 2850,10097.5 Q1.B
NetC23_2: C23.2 C34.2 Q2.B R14.2 R26.1 Z2.K | length 2014.3
  Top Layer w30: C23.2 1700,9800 v1(1750,9750)
  Bottom Layer w30: C34.2 R26.1 1361.48,10163.52 1361.48,10128.52 1420,10070 1490,10070 1570,9990 Z2.K ; Z2.K@1575,9875 C23.2 ; v1(1750,9750) 1772.71,9750 1802.71,9780 2580,9780 2680,9880 2735,9880 Q2.B
NetC24_2: C24.2 C25.2 R6.2 RLY1.2 | length 1403.4
  Bottom Layer w30: C24.2@425,10425 425,10075 525,9975 525,9950 693.63,9781.37 693.63,9706.37 RLY1.2 700,9600 675,9575 R6.2 ; C25.2 425,10435 C24.2@435,10425
NetC28_1: C28.1 R35.1 | length 243.9
  Bottom Layer w30: C28.1 2980,8338.12 3025.62,8292.5 3192.5,8292.5 R35.1
NetC29_1: C29.1 R19.1 R22.2 U2.7 | length 552
  Bottom Layer w30: U2.7 3200,10340 3187.5,10340 3082.5,10445 R22.2 3072.5,10447.5 3072.5,10567.5 R19.1 3073.53,10573.53 3173.53,10573.53 C29.1
NetC29_2: C29.2 R19.2 R21.1 U2.6 | length 535.8
  Bottom Layer w30: R21.1 3211.48,10433.52 3276.48,10433.52 3300,10410 ; U2.6 3300,10410 ; C29.2 R19.2 3460,10570 3300,10410
NetC31_1: C31.1 C33.1 Q2.E R18.1 R25.1 | length 1971.8
  Top Layer w30: R25.1 2600,9900 C33.1
  Bottom Layer w30: R25.1 2675.43,10085.43 ; R18.1 2583.15,10145 2642.71,10085.43 2675.43,10085.43 ; C31.1 3140,11010 3077.57,11010 2905,10837.43 2905,10600 2830,10525 2830,10276.61 2750,10196.61 Q2.E 2740.43,10085.43 2675.43,10085.43
NetC31_2: C31.2 R24.2 | length 210.6
  Top Layer w30: R24.2 2886.48,11011.48 2941.48,11011.48 C31.2
NetC33_2: C33.2 C36.1 R21.2 R25.2 U2.1 | length 1526.2
  Bottom Layer w30: C36.1@2750,9575 2763.39,9588.39 2763.39,9663.39 C33.2 2895,9805 2895,9895 R25.2 2890,9915 2905,9915 3015,10025 U2.1 3100,10145 3135,10180 3540,10180 3600,10240 R21.2
NetC91_1: C91.1 D23.1 R64.1 R65.2 REG1.1 | length 644.1
  Bottom Layer w30: C91.1 925,8690 978.52,8636.48 1038.52,8636.48 R65.2 ; R65.2@1046.56,8616.82 1088.38,8575 D23.1@1222.5,8575 ; REG1.1 1200,8741.24 1225,8716.24 R64.1 1222.5,8697.5 D23.1@1222.5,8575 ; D23.1 D23.1@1222.5,8575
NetC99_1: C99.1 D27.1 R69.1 R70.2 REG3.1 | length 550
  Bottom Layer w30: C99.1@3125,8475 3200,8475 ; R70.2 3200,8475 ; REG3.1 R69.1 D27.1@3200,8550 ; D27.1 D27.1@3200,8550 ; 3200,8475 D27.1@3200,8550
NetC100_2: C100.2 D28.2 R71.1 R72.2 REG4.1 | length 670.1
  Top Layer w20: R71.1 2626.29,8373.71 2626.29,8323.71 C100.2@2630,8320
  Bottom Layer w30: REG4.1@2335,8810.78 2335,8735 R72.2 2336.48,8713.52 2336.48,8660.17 2375,8621.65 D28.2 2473.52,8501.48 2498.52,8501.48 R71.1 ; REG4.1@2344.99,8810.78 REG4.1
NetD1_1: D1.1 P1.2 | length 406.2
  Bottom Layer w50: D1.1 440,8210 P1.2@628.22,8398.22
NetD2_1: D2.1 L1.2 R41.1 U4.4 | length 1212
  Top Layer w60: R41.1 1325.74,7355.74 1325.74,7475.74 L1.2@1430,7580 ; L1.2 1661.33,7600 ; D2.1 1852.74,7712.74 1715,7712.74 1661.33,7659.06 1661.33,7580 1766.33,7475 U4.4
NetD4_A: D4.A D6.K D7.K Q1.C R28.1 R30.2 U2.3 | length 1201.6
  Top Layer w30: Q1.C 2951.71,10292.16 2951.71,10228.29 3000,10180 3190,10180 3290.43,10079.57 3290.43,10034.57 U2.3
  Bottom Layer w30: R30.2 3300,9900 ; D7.K 3300,9900 ; U2.3 3300,9900 ; D4.A D6.K 3505,9800 3405,9900 R28.1 3300,9900
NetD4_K: D4.K D6.A D8.K Q2.C R28.2 R32.2 U2.2 | length 1423.2
  Top Layer w30: Q2.C 2966.24,10095 3001.24,10130 3170,10130 3200,10100 U2.2
  Bottom Layer w30: R32.2 D8.K ; U2.2 3200,10001.47 3100,9901.47 D8.K ; D4.K D6.A R28.2 3388.52,9511.48 3388.52,9561.36 3158.58,9791.3 3108.7,9791.3 D8.K
NetD13_1: D13.1 L3.2 U3.4 | length 542.6
  Bottom Layer w60: L3.2 3270,7810 ; D13.1 3270,7810 ; U3.4 3500,7995.19 3495.58,7990.76 3495.58,7920.58 3385,7810 3270,7810
NetD15_A: D15.A D17.K R31.1 U1.1 U1.2 | length 929.3
  Top Layer w30: U1.2 1850.43,10040.43 1850.43,9987.86 1850,9987.43 1850,9875 2015,9710 2020,9710 2020,9700 R31.1
  Bottom Layer w30: U1.1 U1.2 ; R31.1 2036.48,9688.52 2036.48,9623.52 2148.52,9511.48 2161.48,9511.48 2175,9525 D17.K
NetP3_1: P3.1 RLY1.1 Z5.K | length 994.3
  Bottom Layer w30: RLY1.1@625,9700 497.57,9700 450,9652.43 450,9582.47 557.47,9475 712.37,9475 812.37,9375 971.62,9375 1015.43,9331.19 1015.43,9284.57 P3.1
NetP3_2: P3.2 R10.1 | length 432
  Bottom Layer w30: R10.1@625,9062.37 787.37,9062.37 925,9200 P3.2
NetP5_2: P5.2 R42.1 | length 634.7
  Bottom Layer w30: P5.2 3480,10830 R42.1
NetP10_2: P10.2 R12.2 R13.2 | length 2196.2
  Top Layer w30: v2(375,10300) v2(489.23,10300)
  Bottom Layer w30: v2(375,10300) 375,9600.9 475,9500.9 475,9425 425,9375 425,9225 475,9175 475,9025 400,8950 P10.2 ; v2(489.23,10300) 494.64,10300 514.64,10320 620,10320 690,10390 R12.2 R13.2
NetQ1_E: Q1.E R1.1 R1.2 R17.1 R22.1 | length 1955
  Bottom Layer w30: R17.1 2450,10240 2503.87,10293.87 2675.43,10293.87 ; Q1.E 2675.43,10293.87 ; R1.2@3150,11439.9 3249.9,11439.9 R1.1 ; R1.2 3146.66,11436.66 3146.66,11357.57 3129.08,11340 2967.57,11340 2950,11322.43 2950,10945 2850,10845 2850,10620 R22.1 2675.43,10444.57 2675.43,10293.87
NetR1_3: R1.3 R24.1 | length 191.6
  Bottom Layer w30: R24.1 3010,11400 R1.3
NetR4_1: R4.1 R39.2 U4.2 | length 889.6
  Top Layer w20: v2(2080,7890) 2110,7860 v2(2110,7740)
  Bottom Layer w20: v2(2080,7890) 2080,8070 R4.1 R39.2 ; v2(2110,7740) 2150,7700 U4.2
NetR9_1: R9.1 RLY1.7 | length 396.7
  Bottom Layer w30: RLY1.7 909.57,9990.43 909.57,9945.79 930.36,9925 1077.47,9925 1110,9957.53 R9.1 ; RLY1.7@925,9976.47 RLY1.7@925,10000
NetR9_2: R9.2 RLY1.4 | length 380.7
  Bottom Layer w30: RLY1.4 900,9750 925,9775 1085,9775 1110,9750 R9.2
NetR35_2: R35.2 U3.1 | length 280.6
  Bottom Layer w30: U3.1@3375,8200 U3.1 3390,8195 3495,8300 R35.2
NetR36_1: R36.1 R37.2 U3.2 | length 842.6
  Bottom Layer w30: R37.2 R36.1 2830,8160 3160,8160 3216.47,8103.53 3278.53,8103.53 3305,8130 U3.2
NetR38_2: R38.2 U4.1 | length 315
  Bottom Layer w30: U4.1@2215,7611.47 U4.1 2215,7585 2320,7480 R38.2
NetZ1_A: Z1.A Z4.A | length 100
  Bottom Layer w30: Z1.A Z4.A
NetZ2_A: Z2.A Z3.A | length 90
  Bottom Layer w30: Z2.A Z3.A
pads on no net: P1.3 RLY1.5 RLY1.6

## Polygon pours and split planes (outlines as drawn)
GND on Top Layer "GND_L01_P000" (solid, pour order 0): 375,11325 600,11325 600,11575 3400,11575 3400,11325 3625,11325 3625,7325 375,7325
GND on Bottom Layer "GND_L02_P001" (solid, remove dead copper, pour order 1): 2825,11579.51 3325,11579.51 3325,10979.51 3598.34,10979.51 3624.53,11005.7 3625,11005.23 3625,8640 375,8640 375,10929.51 650,10929.51 650,11579.51 800,11579.51 800,10629.51 2825,10629.51

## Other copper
Top Layer:
  pour cut-out: 2825,10625 2825,11600 800,11600 800,10625
  pour cut-out: 2214.18,8380 1795,8380 1695,8480 1045,8480 888.52,8636.48 343.48,8636.48 338.64,8600 875,8600 1025,8450 1665,8450 1780.41,8334.59 2202.02,8334.59 2321.61,8215 2456.71,8215 2456.71,8240 2354.18,8240
  pour cut-out: 3690,7325 3690,7822.26 3350,7822.26 3350,7325
  pour cut-out: 3650,8025 3450,8025 3305,7880 3135.7,7880 3000,7744.3 3000,7300 3650,7300
  pour cut-out: 900,7855.93 1035.64,7991.57 1300,7991.57 1880,7991.57 1880,7525 2042.65,7525 2050,7517.65 2050,7325 2075,7300 1300,7300 1000,7300 990,7310 990,7660 900,7750
  pour cut-out: 333.89,11346.57 333.89,11027.74 375.96,10985.66 581.99,10985.66 641.96,11045.63 641.96,11350 337.31,11350
  pour cut-out: 3677.5,7273.75 3675,7276.25 3675,7500 3450,7500 3450,7273.75
  pour cut-out: 650,7271.57 650,7521.57 333.89,7521.57 333.89,7271.57
  pour cut-out: 625.13,11346.57 625.13,11596.57 333.89,11596.57 333.89,11346.57
  pour cut-out: 3675,11350 3672.5,11352.5 3672.5,11600 3382.69,11600 3382.69,11350
  pour cut-out: 2837.5,8375 3675,8375 3675,8350 2837.5,8350
  pour cut-out: 3339.34,11375 3672.5,11375 3672.5,10985.64 3339.34,10985.64
  pour cut-out: 645,7507.5 645,7832.5 334.5,7832.5 334.5,7507.5
Bottom Layer:
  pour cut-out: 2837.5,8350 3675,8350 3675,8375 2837.5,8375
  pour cut-out: 325,11375 650,11375 650,11000 325,11000
  pour cut-out: 3300,11375 3647.5,11375 3647.5,11000 3300,11000
  pour cut-out: 2040,8400 2043.5,8403.5
  pour cut-out: 650,7500 650,7840 332,7840 332,7500
  pour cut-out: 3686.25,7470 3686.25,7825 3350,7825 3350,7470

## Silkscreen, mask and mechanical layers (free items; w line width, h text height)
Top Overlay:
  circle w10: c2625,9325 r60.83
  circle w10: c3525,11175 r150
  circle w10: c475,11175 r150
  circle w10: c475,7650 r150
  circle w10: c3525,7650 r150
  lines w10: 550,11595 550,11375 325,11375 325,7500 550,7500 550,7275 3450,7275 3450,7500 3675,7500 3675,11375 3450,11375 3450,11600 2800,11600 2800,10650 850,10650 850,11600 550,11600
  text "G" at 642,11508 h50 r90
  text "H" at 642,11408 h50 r90
  text "C" at 642,11308 h50 r90
  text "A K" at 3300,10720 h60 r90
  text "63V" at 790.43,10510.72 h55
  text "63V" at 435.43,10460.72 h55
  text "#" at 3078,9868 h50
  text "#" at 3284.48,9868 h50
  text "#" at 3498.43,9868 h50
  text "#" at 3598,9868 h50
  text "#" at 2088,9583 h50
  text "#" at 2088,9478 h50
  text "#" at 2088,9383 h50
  text "#" at 2087.26,9283.74 h50
  text "63V" at 1548,9278 h40
  text "GND" at 2573,9203 h40
  text "63V" at 535.43,9160.72 h55
  text "G" at 1968,9118.88 h50
  text "*" at 2068,9099.67 h50
  text "*" at 3608,9049.58 h50
  text "*" at 1507.35,8974.67 h50
  text "63V" at 763,8841.67 h55
  text "63V" at 808,8753 h45
  text "*" at 2256.52,8604.06 h50
  text "*" at 1649.24,8540.41 h50
  text "TGM was here" at 358,8508 h40
  text "*" at 3488,8454.67 h50
  text "V2.1" at 374,8349 h40
  text "2023-05" at 374,8227 h40
  text "9V DC" at 340,8148 h50
  text "* 1N4004" at 1448,7398 h45
  text "63V" at 2568,7348 h55
  text "# 1N914" at 1448,7318 h45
